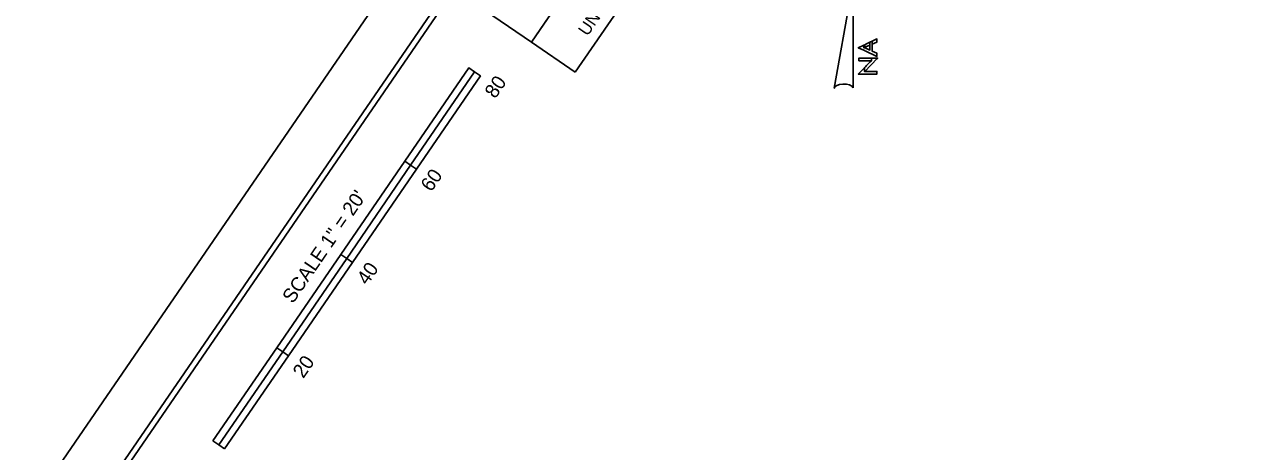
# Model space of a CAD drawing. Extents: x 1439200 to 1641636, y 393269 to 606444.
# Drawn here: x 1641111.2 to 1641330.1, y 393848 to 393923.4 of the extents above; entities that cross this region are included whole.
import ezdxf

# ---------------------------------------------------------------- set-up
doc = ezdxf.new("R2010")
doc.units = 0
for name, color, linetype in [('North Arrow NAD83 CELL', 7, 'Continuous'), ('Old_Level_20', 7, 'Continuous'), ('Old_Level_60', 7, 'Continuous'), ('Sheet Plot Border Inside CELL', 7, 'Continuous'), ('Sheet Plot Border Outside CELL', 7, 'Continuous'), ('Sheet Sticker Exception Certification CELL', 7, 'Continuous'), ('UC Plan Sheet 34 CELL', 7, 'Continuous')]:
    doc.layers.add(name, color=color, linetype=linetype)

msp = doc.modelspace()

# ---------------------------------------------------------------- linework, layer by layer
at = {"layer": 'North Arrow NAD83 CELL'}
for p, q in [((1641257.64, 393931.12), (1641254.3, 393912.22)), ((1641257.66, 393912.3), (1641257.64, 393931.12))]:
    msp.add_line(p, q, dxfattribs=at)
for points in [[(1641261.03, 393918.22), (1641261.85, 393917.84), (1641261.85, 393918.38), (1641261.03, 393918.75), (1641261.03, 393920.54), (1641260.6, 393920.34), (1641260.6, 393918.94), (1641259.88, 393919.27), (1641259.87, 393919.27), (1641259.69, 393919.34), (1641259.69, 393919.34), (1641259.51, 393919.38), (1641259.51, 393919.83), (1641258.54, 393919.38), (1641259.51, 393918.93), (1641259.69, 393918.85), (1641259.69, 393918.84), (1641259.87, 393918.76), (1641259.88, 393918.76), (1641260.6, 393918.42)], [(1641259.88, 393919.51), (1641260.6, 393919.83), (1641260.6, 393920.34), (1641259.87, 393920), (1641259.87, 393920), (1641259.69, 393919.91), (1641259.69, 393919.91), (1641259.69, 393919.44), (1641259.69, 393919.44), (1641259.87, 393919.51)], [(1641261.03, 393920.01), (1641261.85, 393920.37), (1641261.85, 393920.92), (1641261.03, 393920.54)], [(1641259.51, 393919.38), (1641259.69, 393919.44), (1641259.69, 393919.91), (1641259.51, 393919.83)], [(1641260.88, 393914.7), (1641261.85, 393914.7), (1641261.85, 393915.17), (1641260.88, 393915.17), (1641260.67, 393915.17), (1641260.49, 393915.17), (1641260, 393915.17), (1641259.8, 393915.17), (1641259.64, 393915.17), (1641259.64, 393915.83), (1641258.55, 393914.7), (1641259.64, 393914.7), (1641259.81, 393914.7), (1641260, 393914.7), (1641260.49, 393914.7), (1641260.67, 393914.7)], [(1641260.67, 393917.06), (1641260.88, 393917.06), (1641260.88, 393917.54), (1641260.67, 393917.54), (1641260.49, 393917.54), (1641259.99, 393917.54), (1641259.8, 393917.54), (1641258.67, 393917.54), (1641258.67, 393917.06), (1641259.8, 393917.06), (1641259.99, 393917.06), (1641260.49, 393917.06)], [(1641261.85, 393917.41), (1641261.98, 393917.54), (1641261.85, 393917.54), (1641260.88, 393917.54), (1641260.88, 393917.06), (1641260.67, 393916.89), (1641260.49, 393916.72), (1641260, 393916.2), (1641259.8, 393916), (1641259.64, 393915.83), (1641259.64, 393915.17), (1641259.8, 393915.3), (1641260, 393915.48), (1641260.49, 393915.99), (1641260.67, 393916.18), (1641260.88, 393916.39)]]:
    msp.add_lwpolyline(points, close=True, dxfattribs=at)
msp.add_ellipse((1641255.99, 393912.16), major_axis=(1.69, -0.01), ratio=0.461098, start_param=0.201328, end_param=3.141593, dxfattribs=at)
at = {"layer": 'Old_Level_20'}
for points in [[(1641179.4, 393898.6), (1641190.71, 393915.1), (1641189.68, 393915.8), (1641178.37, 393899.31), (1641179.4, 393898.6)], [(1641169.12, 393881.4), (1641180.43, 393897.9), (1641179.4, 393898.6), (1641168.09, 393882.11), (1641169.12, 393881.4)], [(1641156.78, 393865.61), (1641168.09, 393882.11), (1641167.06, 393882.81), (1641155.75, 393866.32), (1641156.78, 393865.61)], [(1641146.5, 393848.41), (1641157.81, 393864.91), (1641156.78, 393865.61), (1641145.47, 393849.12), (1641146.5, 393848.41)]]:
    msp.add_lwpolyline(points, dxfattribs=at)
for points in [[(1641179.4, 393898.6), (1641190.71, 393915.1), (1641191.74, 393914.39), (1641180.43, 393897.9)], [(1641167.06, 393882.81), (1641178.37, 393899.31), (1641179.4, 393898.6), (1641168.09, 393882.11)], [(1641156.78, 393865.61), (1641168.09, 393882.11), (1641169.12, 393881.4), (1641157.81, 393864.91)], [(1641144.44, 393849.83), (1641155.75, 393866.32), (1641156.78, 393865.61), (1641145.47, 393849.12)]]:
    msp.add_lwpolyline(points, close=True, dxfattribs=at)
at = {"layer": 'Old_Level_60'}
msp.add_lwpolyline([(1641187.09, 393929.71), (1641232.34, 393995.7), (1641246, 393986.33), (1641200.74, 393920.34)], close=True, dxfattribs=at)
at = {"layer": 'Sheet Plot Border Inside CELL'}
msp.add_lwpolyline([(1641279.54, 394066.32), (1640902.54, 393516.56), (1641250.61, 393277.88), (1641627.6, 393827.64)], close=True, dxfattribs=at)
at = {"layer": 'Sheet Plot Border Outside CELL'}
msp.add_lwpolyline([(1641273.15, 394072.88), (1640892.2, 393517.35), (1641255.07, 393268.51), (1641636.02, 393824.04)], close=True, dxfattribs=at)
at = {"layer": 'Sheet Sticker Exception Certification CELL'}
for p, q in [((1641200.74, 393920.34), (1641246, 393986.33)), ((1641253.75, 393981.02), (1641208.5, 393915.03)), ((1641208.5, 393915.03), (1641200.74, 393920.34))]:
    msp.add_line(p, q, dxfattribs=at)
at = {"layer": 'UC Plan Sheet 34 CELL'}
msp.add_lwpolyline([(1641277.55, 394061.62), (1640938.22, 393566.79), (1641284.6, 393329.26), (1641623.93, 393824.09)], close=True, dxfattribs=at)

# ---------------------------------------------------------------- texts
at = {"layer": 'Old_Level_20'}
for s, p in [('80', (1641194.36, 393910.24)), ('60', (1641183.05, 393893.75)), ('SCALE 1" = 20\'', (1641158.58, 393873.99)), ('40', (1641171.74, 393877.25)), ('20', (1641160.42, 393860.76))]:
    msp.add_text(s, height=2.5, rotation=55.5597, dxfattribs=at).set_placement(p)
at = {"layer": 'Sheet Sticker Exception Certification CELL'}
msp.add_text('UNLESS ALL SIGNATURES COMPLETED', height=2.2, rotation=55.5597, dxfattribs=at).set_placement((1641210.68, 393921.29))

doc.saveas('drawing.dxf')
